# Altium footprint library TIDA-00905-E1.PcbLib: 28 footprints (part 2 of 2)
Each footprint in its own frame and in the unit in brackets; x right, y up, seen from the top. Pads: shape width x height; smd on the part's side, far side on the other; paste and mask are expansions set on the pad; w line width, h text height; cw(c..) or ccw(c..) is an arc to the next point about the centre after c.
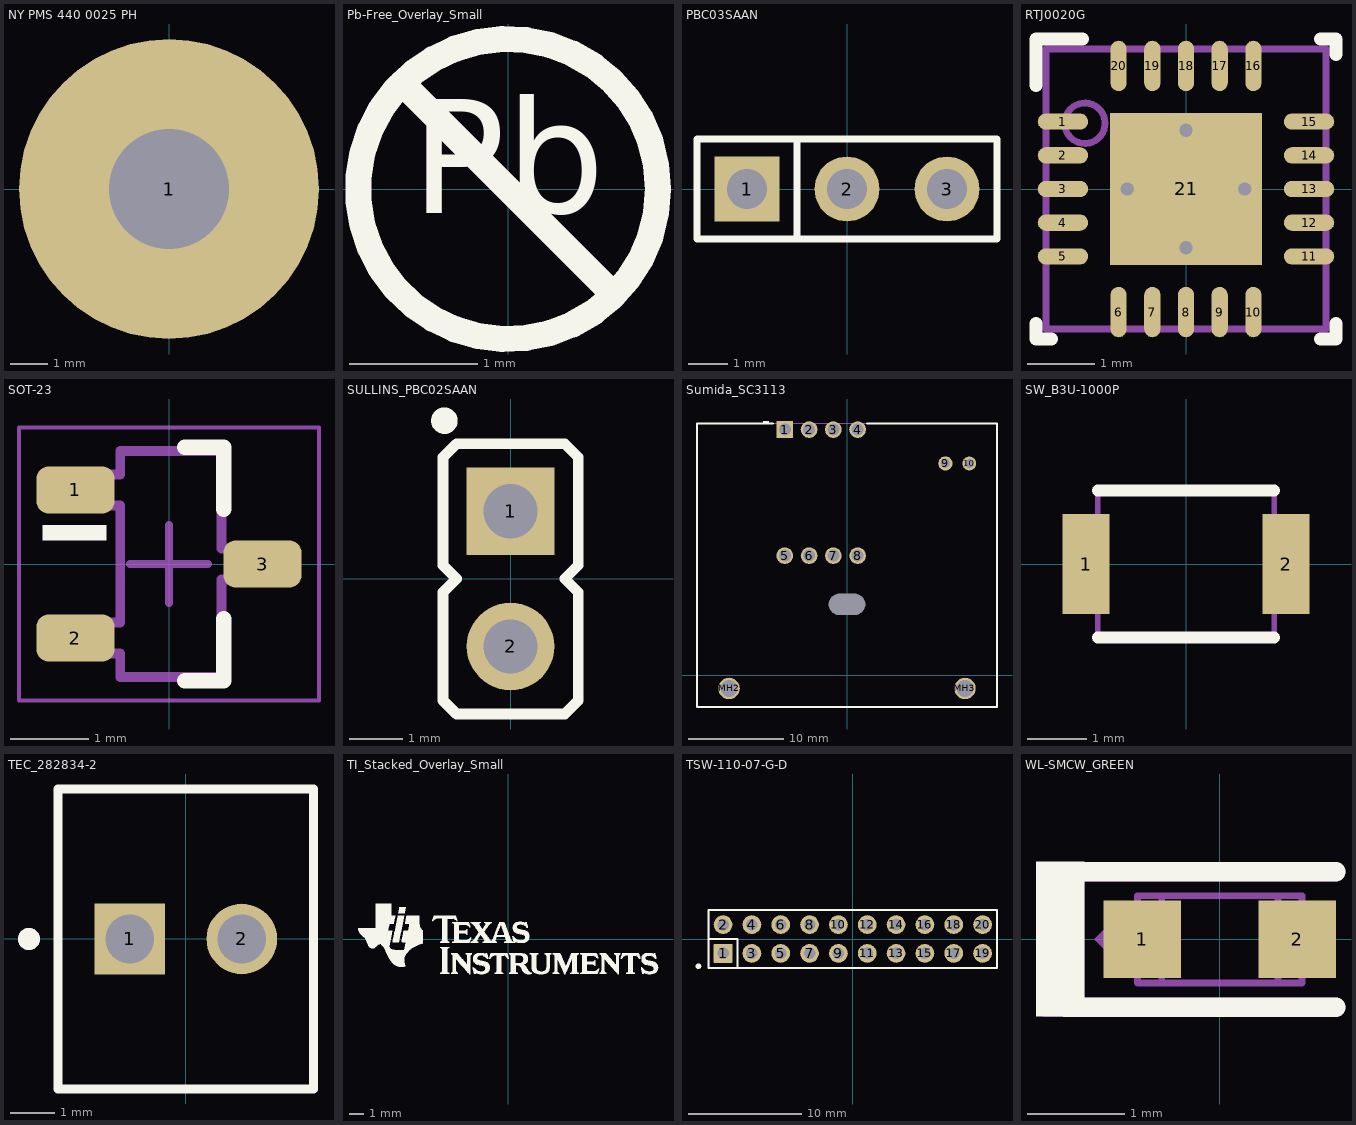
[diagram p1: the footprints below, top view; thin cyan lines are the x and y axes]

## NY PMS 440 0025 PH [mm] "4-40 nylon screw and mounting hole"
height 1.905
pads (1):
  round 8 hole 3.2: 1(0,0)
Mechanical 5:
  circle w0.127: c0,0 r3.789
  text ".Designator" at -1.524,-0.508 h0.76
3D body: height 2.69, standoff -8.74, extent -3.302,-3.3 3.296,3.3

## Pb-Free_Overlay_Small [mm]
height 0.85
Top Overlay:
  circle w0.203: c0,0 r1.168
  lines w0.203: -0.826,0.826 0.826,-0.826
  text "Pb" at -0.752,-0.48 h1.52

## PBC03SAAN [mm] "Sullins 100mil, 1x3, 230 mil above insulator"
height 8.382
pads (3):
  rect 1.65x1.65 hole 1.016: 1(-2.54,0)
  round 1.65 hole 1.016: 2(0,0) 3(2.54,0)
Top Overlay:
  lines w0.178: -1.27,-1.27 -1.27,1.27 ; -3.81,-1.27 -3.81,1.27 3.81,1.27 3.81,-1.27 -3.81,-1.27
Mechanical 5:
  rectangle: -3.048,-0.508 -2.032,0.508
  lines w0.127: -3.81,-1.27 3.81,-1.27 3.81,1.27 -3.81,1.27 -3.81,-1.27
  text ".Designator" at -0.88,-0.535 h0.76
3D body: height 8.38, standoff -3.05, extent -3.81,-1.27 3.81,1.27

## RTJ0020G [mm] "QFN, 20-Leads, Body 4x4mm, Pitch 0.5mm, Thermal Pad 2.25x2.25mm, TI Recommended"
height 0.8
pads (21):
  oval 0.75x0.24 smd: 1(-1.825,1) 2(-1.825,0.5) 3(-1.825,0) 4(-1.825,-0.5) 5(-1.825,-1) 11(1.825,-1) 12(1.825,-0.5) 13(1.825,0) 14(1.825,0.5) 15(1.825,1)
  oval 0.24x0.75 smd: 6(-1,-1.825) 7(-0.5,-1.825) 8(0,-1.825) 9(0.5,-1.825) 10(1,-1.825) 16(1,1.825) 17(0.5,1.825) 18(0,1.825) 19(-0.5,1.825) 20(-1,1.825)
  rect 2.25x2.25 smd paste-1.125: 21(0,0)
via 0.875,0 diameter 0.5 hole 0.2
via 0,-0.875 diameter 0.5 hole 0.2
via -0.875,0 diameter 0.5 hole 0.2
via 0,0.875 diameter 0.5 hole 0.2
Top Overlay:
  lines w0.2: -2.225,-2 -2.225,-2.225 -2,-2.225 ; -2.225,1.54 -2.225,2.225 -1.54,2.225 ; 2,-2.225 2.225,-2.225 2.225,-2 ; 2,2.225 2.225,2.225 2.225,2
Top Paste:
  rectangle: 0.1,0.1 1.1,1.1
  region: -0.1,1.1 -1.1,1.1 -1.1,0.1 -0.1,0.1
  region: -0.1,-0.1 -1.1,-0.1 -1.1,-1.1 -0.1,-1.1
  rectangle: 0.1,-1.1 1.1,-0.1
Mechanical 5:
  circle w0.1: c-1.5,0.975 r0.3
  lines w0.1: -2.075,-2.075 2.075,-2.075 2.075,2.075 -2.075,2.075 -2.075,-2.075
  text ".Designator" at -0.381,0.686 h0.76
3D body: height 0.8, standoff 0, extent -2.075,-2.075 2.075,2.075
3D body: height 0.81, standoff 0.5, extent -1.805,0.67 -1.195,1.28

## SOT-23 [mm] "SOT23, 3-Leads, Body 2.9x1.3mm, Pitch 0.95mm, Lead Span 2.5mm, IPC Medium Density"
height 1.1
pads (3):
  rrect50% 1x0.6 smd: 1(-1.2,0.95) 2(-1.2,-0.95) 3(1.2,0)
Top Overlay:
  rectangle: -1.625,0.3 -0.8,0.5
  lines w0.2: 0.2,-1.5 0.7,-1.5 0.7,-0.7 ; 0.2,1.5 0.7,1.5 0.7,0.7
Mechanical 5:
  lines w0.127: -1.16,-1.15 -0.625,-1.15 -0.625,-1.45 0.675,-1.45 0.675,-0.2 1.21,-0.2 1.21,0.2 0.675,0.2 0.675,1.45 -0.625,1.45 -0.625,1.15 -1.16,1.15 -1.16,0.75 -0.625,0.75 -0.625,-0.75 -1.16,-0.75 -1.16,-1.15
  text ".Designator" at 0.33,-0.711 h0.76
Mechanical 15:
  lines w0.05: -1.925,-1.75 -1.925,1.75 1.925,1.75 1.925,-1.75 -1.925,-1.75
  lines w0.1: -0.5,0 0.5,0 ; 0,-0.5 0,0.5
3D body: height 1, standoff 0, extent -1.16,-1.45 1.21,1.45

## SULLINS_PBC02SAAN [mm] "Sullins 100mil, 1x2, 230 mil above insulator"
height 8.382
pads (2):
  rect 1.65x1.65 hole 1.016: 1(0,1.27)
  round 1.65 hole 1.016: 2(0,-1.27)
Top Overlay:
  circle w0.25: c-1.245,2.972 r0.125
  lines w0.2: -1.27,-2.286 -1.27,-0.254 -1.016,0 -1.27,0.254 -1.27,2.286 -1.016,2.54 1.016,2.54 1.27,2.286 1.27,0.254 1.016,0 1.27,-0.254 1.27,-2.286 1.016,-2.54 -1.016,-2.54 -1.27,-2.286
Mechanical 5:
  circle w0.254: c0,1.27 r0.284
  lines w0.1: -1.27,-2.286 -1.016,-2.54 1.016,-2.54 1.27,-2.286 1.27,-0.254 1.016,0 1.27,0.254 1.27,2.286 1.016,2.54 -1.016,2.54 -1.27,2.286 -1.27,0.254 -1.016,0 -1.27,-0.254 -1.27,-2.286
  text ".Designator" at -0.635,-0.762 h0.76
3D body: height 2.54, standoff 0, extent -1.27,-2.54 1.27,2.54
3D body: height 8.38, standoff -3.05, extent -0.317,-1.587 0.317,-0.953
3D body: height 8.38, standoff -3.05, extent -0.317,0.953 0.317,1.587

## Sumida_SC3113 [mm] "TH, 10-Leads, Body 31.3x29.6mm"
height 13.4
pads (13):
  rect 1.75x1.75 hole 1.25: 1(-6.51,25.7)
  round 1.75 hole 1.25: 2(-3.97,25.7) 3(-1.43,25.7) 4(1.11,25.7) 5(-6.51,12.5) 6(-3.97,12.5) 7(-1.43,12.5) 8(1.11,12.5)
  round 1.5 hole 1: 9(10.3,22.15)
  round 1.45 hole 0.95: 10(12.8,22.15)
  round 0 hole 2.2 slot 3.8 at 0 deg: MH1(0,7.4)
  round 2.25 hole 1.75: MH2(-12.35,-1.4) MH3(12.35,-1.4)
Top Overlay:
  region: -8.153,26.603 -8.788,26.603 -8.788,26.324 -8.153,26.324
  lines w0.2: -7.722,26.349 -15.7,26.35 -15.7,-3.35 15.7,-3.35 15.7,26.35 2.083,26.349
Mechanical 5:
  region: -8.153,26.603 -8.788,26.603 -8.788,26.324 -8.153,26.324
  lines w0.1: -15.7,-3.35 -15.7,26.35 15.7,26.35 15.7,-3.35 -15.7,-3.35
  text ".Designator" at -0.333,12.126 h0.76
3D body: height 13.3, standoff -3.5, extent -15.7,-3.35 15.7,26.35

## SW_B3U-1000P [mm] "OMRON"
height 1.75
pads (2):
  rect 0.8x1.7 smd: 1(-1.7,0) 2(1.7,0)
Top Overlay:
  lines w0.2: -1.5,-1.25 1.5,-1.25 ; -1.5,1.25 1.5,1.25
Mechanical 5:
  lines w0.1: -1.5,-0.7 -2,-0.7 -2,0.7 -1.5,0.7 ; 1.5,-0.7 2,-0.7 2,0.7 1.5,0.7 ; -1.5,-1.25 -1.5,1.25 1.5,1.25 1.5,-1.25 -1.5,-1.25
  text ".Designator" at 0.635,0.381 h0.76
3D body: height 1.35, standoff 0, extent -1.5,-1.25 1.5,1.25
3D body: height 1.75, standoff 0.01, extent -0.756,-0.756 0.756,0.756

## TEC_282834-2 [mm] "TEC"
height 10.3
pads (2):
  rect 1.6x1.6 hole 1.1: 1(-1.27,0)
  round 1.6 hole 1.1: 2(1.27,0)
Top Overlay:
  circle w0.3: c-3.556,0 r0.1
  lines w0.2: -2.895,-3.4 -2.895,3.4 2.895,3.4 2.895,-3.4 -2.895,-3.4
Mechanical 5:
  circle w0.3: c-3.556,0 r0.1
  lines w0.1: -2.895,-3.4 -2.895,3.4 2.895,3.4 2.895,-3.4 -2.895,-3.4
  text ".Designator" at -0.686,1.041 h0.76
3D body: height 10.01, standoff -3.39, extent -2.77,-3.25 2.77,3.25

## TI_Stacked_Overlay_Small [mm]
height 0.85
Top Overlay:
  drawing of 18 lines, arcs and shapes, not listed

## TSW-110-07-G-D [mm] "Samtec 100mil, 2x10, 230 mil above insulator"
height 8.382
pads (20):
  rrect6% 1.65x1.65 hole 1.016: 1(-11.43,-1.27)
  round 1.65 hole 1.016: 2(-11.43,1.27) 3(-8.89,-1.27) 4(-8.89,1.27) 5(-6.35,-1.27) 6(-6.35,1.27) 7(-3.81,-1.27) 8(-3.81,1.27) 9(-1.27,-1.27) 10(-1.27,1.27) 11(1.27,-1.27) 12(1.27,1.27) 13(3.81,-1.27) 14(3.81,1.27) 15(6.35,-1.27) 16(6.35,1.27) 17(8.89,-1.27) 18(8.89,1.27) 19(11.43,-1.27) 20(11.43,1.27)
Top Overlay:
  circle w0.25: c-13.6,-2.4 r0.125
  lines w0.178: -12.7,0 -10.16,0 -10.16,-2.54 ; -12.7,-2.54 -12.7,2.54 12.7,2.54 12.7,-2.54 -12.7,-2.54
Mechanical 5:
  rectangle: -11.938,-1.778 -10.922,-0.762
  lines w0.127: -12.7,-2.54 12.7,-2.54 12.7,2.54 -12.7,2.54 -12.7,-2.54
  text ".Designator" at -0.686,-0.457 h0.76
3D body: height 8.38, standoff -2.54, extent -12.7,-2.54 12.7,2.54

## WL-SMCW_GREEN [mm] "WURTH"
height 0.8
pads (2):
  rect 0.8x0.8 smd: 1(-0.8,0) 2(0.8,0)
Top Overlay:
  rectangle: -1.9,-0.796 -1.4,0.804
  lines w0.2: -1.6,-0.7 1.2,-0.7 ; -1.6,0.7 1.2,0.7
Mechanical 5:
  region: -0.9,-0.4 -0.9,0.4 -1.3,0
  lines w0.2: -1.65,-0.7 -1.65,0.55 ; 1.2,-0.7 -1.5,-0.7 ; 1.2,0.7 -1.5,0.7 ; -1.5,-0.7 -1.5,0.7 ; -1.5,-0.7 -1.8,-0.7 -1.8,0.7 -1.5,0.7
  text ".Designator" at 0.889,0.319 h0.76
Mechanical 13:
  lines w0.07: -0.6,-0.45 -0.6,0.45 ; 0.6,-0.45 0.6,0.45 ; -0.85,-0.45 -0.85,0.45 0.85,0.45 0.85,-0.45 -0.85,-0.45
3D body: height 0.35, standoff 0, extent -0.849,-0.449 -0.601,0.449
3D body: height 0.35, standoff 0, extent -0.599,-0.449 0.599,0.449
3D body: height 0.35, standoff 0, extent 0.601,-0.449 0.849,0.449
3D body: height 0.8, standoff 0.35, extent -0.599,-0.449 0.599,0.449
3D body: height 0.36, standoff 0.35, extent -0.599,-0.449 0.599,0.449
